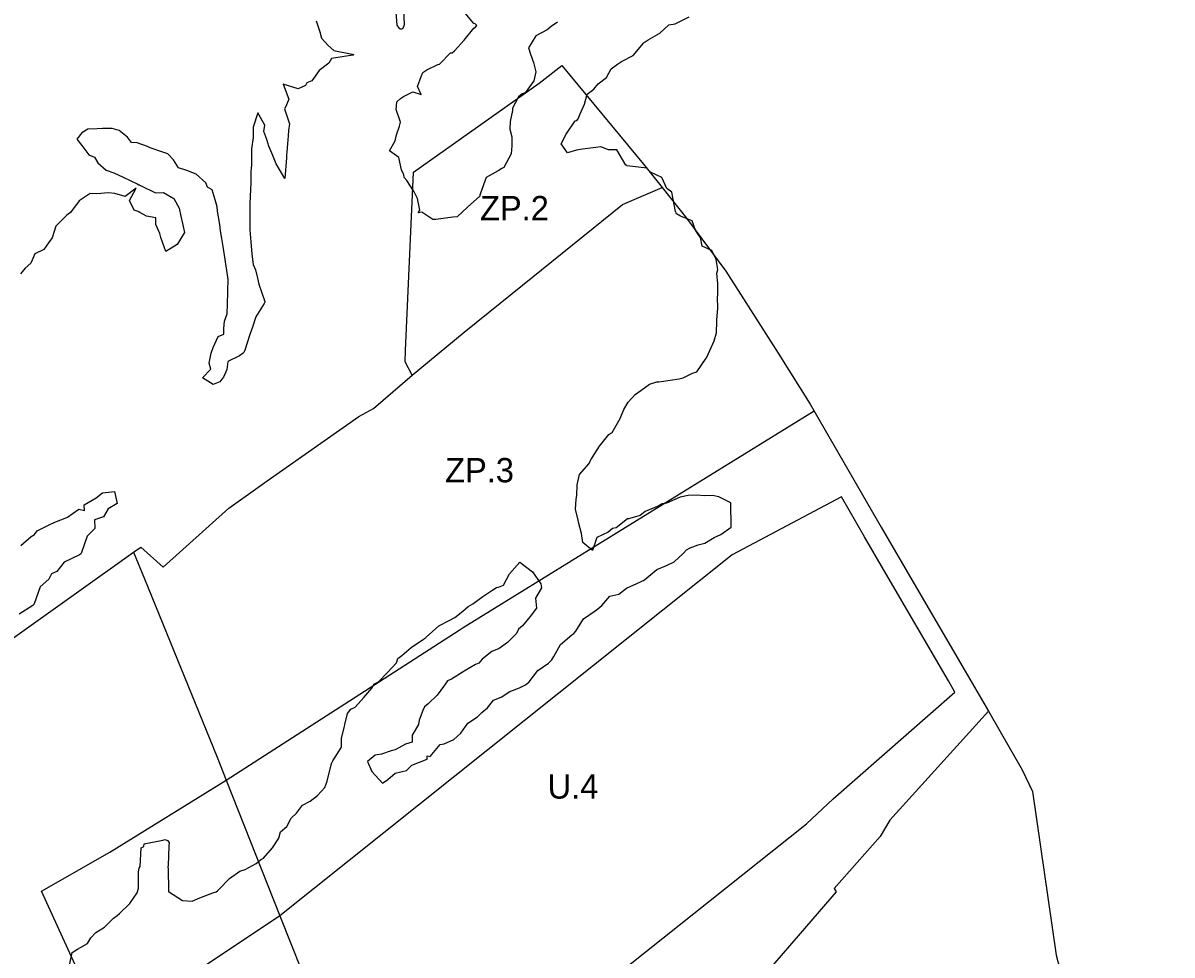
# Model space of a CAD drawing. Extents: x 7423571 to 7425893, y 5544590 to 5545833.
# Drawn here: x 7424591.2 to 7424826.9, y 5545056.2 to 5545247.5 of the extents above; entities that cross this region are included whole.
import ezdxf

# ---------------------------------------------------------------- set-up
doc = ezdxf.new("R2010")
doc.units = 0
for name, color, linetype in [('Default', 7, 'Continuous'), ('linie_rozgraniczające', 7, 'Continuous'), ('linie_zabudowy_nieprzekraczalne', 7, 'Continuous'), ('oznaczenia_przeznaczen', 7, 'Continuous')]:
    doc.layers.add(name, color=color, linetype=linetype)

msp = doc.modelspace()

# ---------------------------------------------------------------- linework, layer by layer
at = {"layer": 'Default'}
for points in [[(7424700.89, 5545247.67), (7424699.56, 5545246.78), (7424698.76, 5545246.07), (7424696.41, 5545244.87), (7424694.93, 5545242.42), (7424695.32, 5545241.07), (7424695.96, 5545239.39), (7424696.42, 5545237.48), (7424696.04, 5545235.6), (7424694.28, 5545233.18), (7424693.65, 5545232.99), (7424692.86, 5545232.33), (7424691.64, 5545230.04), (7424691.68, 5545229.54), (7424691.19, 5545227.26), (7424691.13, 5545225.7), (7424691.52, 5545224.15), (7424691.51, 5545222.27), (7424691.38, 5545220.66), (7424689.89, 5545217.85), (7424689.44, 5545217.64), (7424688.7, 5545217.15), (7424686.24, 5545215.78), (7424685.1, 5545212.58), (7424684.98, 5545212.14), (7424684.98, 5545211.99), (7424682.4, 5545209.71), (7424680.3, 5545207.71), (7424679.41, 5545207.65), (7424675.9, 5545207.21), (7424675.32, 5545207.17), (7424673.08, 5545208.68), (7424672.33, 5545208.56), (7424672.67, 5545209.06), (7424672.19, 5545211.48), (7424671.46, 5545212.83), (7424669.99, 5545215.16), (7424669.42, 5545215.83), (7424669.37, 5545216.36), (7424668.87, 5545217.37), (7424668.35, 5545219.88), (7424666.42, 5545221.25), (7424667.61, 5545223.34), (7424667.84, 5545224.54), (7424668.44, 5545226.33), (7424668.69, 5545227.16), (7424667.8, 5545229.72), (7424667.93, 5545231.32), (7424668.67, 5545231.98), (7424669.29, 5545232.44), (7424671.19, 5545233.39), (7424672.95, 5545232.84), (7424672.19, 5545234.48), (7424672.89, 5545236.52), (7424673.28, 5545237.35), (7424674.07, 5545237.86), (7424676.31, 5545238.95), (7424676.66, 5545239.04), (7424678.93, 5545241.39), (7424679.3, 5545241.41), (7424679.78, 5545241.81), (7424681.75, 5545243.96), (7424683.73, 5545246.47), (7424684.04, 5545246.66), (7424684.32, 5545246.99), (7424684.02, 5545247.3), (7424683.69, 5545247.39), (7424681.62, 5545249.92)], [(7424669.32, 5545250.62), (7424669.4, 5545247.1), (7424669.13, 5545246.38), (7424668.85, 5545246.24), (7424668.73, 5545246.22), (7424668.58, 5545246.21), (7424668.49, 5545246.35), (7424667.96, 5545247.06), (7424667.75, 5545250.53)], [(7424651.36, 5545247.94), (7424652.11, 5545245.69), (7424652.5, 5545244.41), (7424653.85, 5545242.88), (7424654.97, 5545241.88), (7424658.79, 5545241.09), (7424658.93, 5545241.04), (7424658.99, 5545241.02), (7424659.08, 5545240.97), (7424658.96, 5545240.94), (7424658.93, 5545240.93), (7424658.88, 5545240.9), (7424654.54, 5545240.21), (7424654, 5545239.29), (7424652.01, 5545237.72), (7424650.49, 5545235.61), (7424649.49, 5545235.24), (7424649.18, 5545234.67), (7424647.69, 5545233.98), (7424644.59, 5545234.95), (7424645.75, 5545231.87), (7424645.17, 5545230.39), (7424644.88, 5545229.87), (7424645.9, 5545226.83), (7424645.72, 5545225.41), (7424645.62, 5545224.38), (7424645.38, 5545221.04), (7424645.32, 5545220.39), (7424645.3, 5545219.86), (7424644.95, 5545215.57), (7424643.15, 5545218.63), (7424642.49, 5545220.28), (7424641.67, 5545222.24), (7424641.23, 5545223.62), (7424640.65, 5545225.21), (7424640.82, 5545226.54), (7424639.4, 5545229.06), (7424638.49, 5545226.15), (7424638.47, 5545225.12), (7424638.47, 5545223.98), (7424638.09, 5545221.71), (7424638.1, 5545220.1), (7424638.1, 5545218.37), (7424637.99, 5545216.99), (7424638, 5545215.09), (7424637.9, 5545212.94), (7424637.86, 5545212.3), (7424637.77, 5545210.08), (7424637.76, 5545207.58), (7424637.76, 5545207.57), (7424637.76, 5545205.07), (7424637.96, 5545202.59), (7424637.96, 5545202.57), (7424638.18, 5545200.09), (7424638.49, 5545197.92), (7424638.95, 5545196.87), (7424639.33, 5545195.13), (7424639.59, 5545193.91), (7424640.84, 5545190.32), (7424640.87, 5545190.19), (7424640.73, 5545189.92), (7424639.02, 5545187.19), (7424638.33, 5545185.08), (7424637.74, 5545183.56), (7424636.74, 5545180.38), (7424636.61, 5545180.01), (7424636.52, 5545179.88), (7424636.4, 5545179.76), (7424635.65, 5545179.2), (7424633.29, 5545178.05), (7424633.04, 5545176.37), (7424632.34, 5545174.83), (7424632, 5545174.43), (7424631.63, 5545173.9), (7424630.22, 5545173.3), (7424628.07, 5545174.66), (7424629.77, 5545176.48), (7424629.46, 5545177.7), (7424629.87, 5545179.73), (7424630.22, 5545180.88), (7424631.25, 5545183.19), (7424632.42, 5545183.65), (7424632.45, 5545184.84), (7424632.57, 5545186.29), (7424633.11, 5545187.83), (7424633.16, 5545189.88), (7424633.23, 5545192.22), (7424633.24, 5545192.51), (7424633.31, 5545194.89), (7424632.97, 5545197.16), (7424632.91, 5545197.63), (7424632.58, 5545199.86), (7424632.32, 5545201.67), (7424632.03, 5545203.25), (7424631.79, 5545204.83), (7424631.65, 5545206.15), (7424631.16, 5545208.86), (7424631.05, 5545209.81), (7424630.89, 5545210.55), (7424630.03, 5545213.28), (7424629.1, 5545213.82), (7424628.76, 5545214.72), (7424626.74, 5545216.48), (7424624.87, 5545217.24), (7424623.12, 5545217.77), (7424622.12, 5545219.45), (7424620.98, 5545220.65), (7424619.71, 5545221.08), (7424617.33, 5545221.91), (7424616.77, 5545222.13), (7424614.63, 5545222.92), (7424613.53, 5545223.01), (7424612.68, 5545224.07), (7424610.94, 5545225.42), (7424609.51, 5545225.88), (7424607.55, 5545225.83), (7424606.44, 5545225.75), (7424604.51, 5545225.7), (7424603.28, 5545224.95), (7424602.26, 5545223.65), (7424603.29, 5545222.33), (7424604.72, 5545220.47), (7424605.9, 5545219.95), (7424606.61, 5545218.82), (7424608.29, 5545217.32), (7424609.88, 5545216.78), (7424611.77, 5545215.89), (7424614.64, 5545214.47), (7424614.98, 5545214.31), (7424615.14, 5545214.32), (7424615.34, 5545214.17), (7424618.43, 5545212.68), (7424620.05, 5545212.72), (7424622.17, 5545211.52), (7424623.31, 5545209.49), (7424623.62, 5545207.87), (7424624.13, 5545205.73), (7424624.37, 5545204.53), (7424622.88, 5545202.07), (7424620.54, 5545200.63), (7424619.54, 5545203.46), (7424619.34, 5545204.33), (7424618.49, 5545206.12), (7424618.51, 5545207.54), (7424616.61, 5545207.85), (7424615.21, 5545208.64), (7424614.85, 5545208.8), (7424614.07, 5545209.12), (7424613.11, 5545211.08), (7424614.45, 5545213.58), (7424612.19, 5545211.93), (7424610.05, 5545212.53), (7424608.77, 5545212.63), (7424606.41, 5545212.45), (7424605.04, 5545212.52), (7424602.79, 5545210.98), (7424601.01, 5545208.59), (7424600.5, 5545208.28), (7424600.22, 5545208.08), (7424597.95, 5545205.82), (7424597.2, 5545203.43), (7424596.45, 5545202.4), (7424595.5, 5545201.05), (7424593.7, 5545200.12), (7424592.86, 5545198.25), (7424591.67, 5545197.18), (7424590.7, 5545196.02)], [(7424600.81, 5545054.11), (7424601.36, 5545056.79), (7424602.43, 5545057.43), (7424604.45, 5545058.61), (7424605.13, 5545059.75), (7424606.2, 5545060.86), (7424607.94, 5545061.97), (7424609.81, 5545063.83), (7424610.59, 5545064.33), (7424611.04, 5545064.76), (7424613.13, 5545066.8), (7424614.65, 5545069.03), (7424614.92, 5545069.96), (7424614.95, 5545073.3), (7424615.08, 5545074.05), (7424615.29, 5545074.43), (7424615.5, 5545078.25), (7424616.06, 5545078.52), (7424616.12, 5545079.1), (7424619.9, 5545079.79), (7424620.43, 5545079.97), (7424620.89, 5545079.75), (7424621.23, 5545079.31), (7424621.19, 5545078.6), (7424620.99, 5545074.64), (7424620.97, 5545074.29), (7424621, 5545073.97), (7424621.09, 5545069.52), (7424621.11, 5545069.29), (7424623.99, 5545067.46), (7424625.95, 5545067.31), (7424627.5, 5545067.98), (7424630.2, 5545068.98), (7424630.87, 5545069.25), (7424631.17, 5545069.4), (7424631.43, 5545069.71), (7424633.59, 5545071.97), (7424635.71, 5545073.47), (7424636.84, 5545073.79), (7424639.08, 5545075.03), (7424639.93, 5545075.75), (7424640.6, 5545076.15), (7424642.44, 5545078.24), (7424643.74, 5545080.22), (7424644.07, 5545081.55), (7424645.34, 5545082.65), (7424646.24, 5545084.36), (7424647.34, 5545085.37), (7424648.59, 5545087), (7424650.14, 5545087.85), (7424651.63, 5545089.01), (7424653.15, 5545090.61), (7424653.66, 5545091.94), (7424654.45, 5545095.28), (7424654.57, 5545095.67), (7424654.64, 5545095.85), (7424654.8, 5545096.12), (7424656.57, 5545098.88), (7424656.57, 5545100.76), (7424657.17, 5545103.14), (7424657.27, 5545103.55), (7424657.83, 5545105.81), (7424658.52, 5545106.7), (7424659.36, 5545107.13), (7424661.13, 5545109.1), (7424662.83, 5545111.02), (7424663.35, 5545111.87), (7424664.15, 5545112.33), (7424666.01, 5545114.22), (7424667.87, 5545116.23), (7424668.13, 5545117.07), (7424668.94, 5545117.73), (7424670.84, 5545119.38), (7424673.41, 5545121.06), (7424673.8, 5545121.33), (7424673.9, 5545121.37), (7424673.97, 5545121.48), (7424676.51, 5545123.77), (7424678.65, 5545124.92), (7424679.83, 5545125.52), (7424681.49, 5545126.79), (7424682.57, 5545127.8), (7424683.52, 5545128.33), (7424685.59, 5545129.83), (7424687.42, 5545131.04), (7424688.39, 5545131.69), (7424688.77, 5545131.71), (7424689.81, 5545132.13), (7424691.01, 5545134.44), (7424693.18, 5545136.88), (7424695.76, 5545134.87), (7424697.44, 5545132.44), (7424697.59, 5545131.63), (7424696.4, 5545129.48), (7424696.54, 5545127.4), (7424695.28, 5545125.7), (7424693.71, 5545123.81), (7424692.85, 5545123.13), (7424692.47, 5545122.23), (7424690.65, 5545120.36), (7424688.9, 5545119.16), (7424687.41, 5545118.53), (7424685.46, 5545116.94), (7424684.77, 5545116.16), (7424684.03, 5545115.84), (7424681.76, 5545114.47), (7424681.53, 5545114.33), (7424679.14, 5545112.88), (7424678.3, 5545112.51), (7424677.72, 5545111.62), (7424676.23, 5545109.6), (7424674.34, 5545107.82), (7424673.63, 5545107.19), (7424673.24, 5545106.44), (7424672.54, 5545104.47), (7424672.34, 5545103.57), (7424671.04, 5545101.34), (7424671.08, 5545099.92), (7424669.68, 5545099.51), (7424667.58, 5545098.34), (7424666.74, 5545098.18), (7424664.76, 5545097.47), (7424663.51, 5545097.28), (7424661.94, 5545095.97), (7424662.77, 5545093.88), (7424665, 5545091.53), (7424666.08, 5545092.24), (7424667.57, 5545093.55), (7424669.9, 5545094.12), (7424670.99, 5545095.2), (7424674.17, 5545096.47), (7424674.13, 5545097.11), (7424674.78, 5545096.97), (7424676.79, 5545099.47), (7424677.65, 5545099.58), (7424679.65, 5545100.45), (7424680.29, 5545101.06), (7424681.04, 5545101.75), (7424682.47, 5545103.85), (7424684.46, 5545105.11), (7424685.35, 5545106.01), (7424686.52, 5545106.98), (7424687.78, 5545108.57), (7424689.3, 5545109.15), (7424691.12, 5545110.3), (7424693.07, 5545111.09), (7424694.2, 5545111.64), (7424694.62, 5545111.89), (7424695.07, 5545112.33), (7424696.85, 5545114.64), (7424699.03, 5545116.15), (7424699.71, 5545116.8), (7424700.15, 5545117.54), (7424701.53, 5545119.94), (7424703.79, 5545121.95), (7424704.23, 5545122.26), (7424704.67, 5545122.72), (7424706.18, 5545125.27), (7424708.6, 5545126.87), (7424709.17, 5545127.32), (7424709.97, 5545127.94), (7424711.59, 5545129.9), (7424713.46, 5545130.32), (7424715.06, 5545131.51), (7424717.91, 5545132.82), (7424718.35, 5545133.06), (7424718.53, 5545133.12), (7424718.78, 5545133.3), (7424721.29, 5545135.38), (7424723.23, 5545136.18), (7424724.79, 5545136.96), (7424726.68, 5545138.63), (7424727.35, 5545139.41), (7424728.09, 5545139.78), (7424729.75, 5545140.44), (7424731.09, 5545140.77), (7424733, 5545141.95), (7424734.41, 5545142.51), (7424736.47, 5545144.03), (7424736.49, 5545145.41), (7424736.41, 5545147.66), (7424736.42, 5545149.03), (7424733.97, 5545150.24), (7424732.66, 5545150.53), (7424730.99, 5545150.48), (7424729.51, 5545150.61), (7424727.65, 5545150.56), (7424726.07, 5545150.21), (7424723.21, 5545148.99), (7424722.72, 5545148.85), (7424722.38, 5545148.8), (7424721.67, 5545148.43), (7424718.84, 5545147.26), (7424717.81, 5545146.46), (7424715.42, 5545145.76), (7424715.23, 5545145.77), (7424712.91, 5545143.88), (7424712.16, 5545143.8), (7424711.27, 5545143.01), (7424708.95, 5545141.95), (7424708.09, 5545139.29), (7424706.11, 5545140.88), (7424705.77, 5545142.78), (7424705.19, 5545145.09), (7424705.1, 5545145.5), (7424704.55, 5545147.74), (7424704.68, 5545149.76), (7424704.88, 5545150.51), (7424704.93, 5545152.76), (7424705.41, 5545154.83), (7424707.37, 5545157.13), (7424707.61, 5545157.61), (7424707.7, 5545157.87), (7424708.52, 5545159.14), (7424709.47, 5545160.7), (7424711.43, 5545163.03), (7424711.81, 5545163.36), (7424712.12, 5545163.48), (7424713.76, 5545166.37), (7424714.47, 5545168.16), (7424715.35, 5545169.71), (7424716.8, 5545171.27), (7424718, 5545172.08), (7424719.72, 5545173.37), (7424721.24, 5545173.89), (7424721.7, 5545173.85), (7424722.16, 5545173.94), (7424725.82, 5545174.48), (7424726.67, 5545174.66), (7424728.57, 5545175.67), (7424729.47, 5545175.93), (7424731.36, 5545178.7), (7424731.48, 5545178.85), (7424731.49, 5545178.87), (7424731.5, 5545178.93), (7424733.03, 5545182.26), (7424733.49, 5545183.94), (7424733.59, 5545186.33), (7424733.57, 5545186.57), (7424733.74, 5545188.95), (7424733.73, 5545191.23), (7424733.78, 5545191.75), (7424733.79, 5545193.96), (7424733.57, 5545196.19), (7424733.74, 5545196.92), (7424733.42, 5545198.95), (7424732.52, 5545200.82), (7424730.58, 5545201.68), (7424730.18, 5545203.49), (7424729.97, 5545203.81), (7424729.21, 5545205.02), (7424728.5, 5545206.89), (7424726.1, 5545207.88), (7424725.31, 5545208.37), (7424725.22, 5545208.54), (7424725.17, 5545208.62), (7424725.07, 5545208.83), (7424724.34, 5545212.81), (7424723.32, 5545213.55), (7424722.27, 5545215.78), (7424719.96, 5545216.86), (7424719.21, 5545217.68), (7424715.14, 5545218.22), (7424715, 5545218.33), (7424714.89, 5545218.36), (7424713.07, 5545221.45), (7424711.36, 5545221.47), (7424709.74, 5545222.08), (7424708.71, 5545221.93), (7424706.02, 5545221.59), (7424704.76, 5545221.41), (7424702.92, 5545220.87), (7424701.64, 5545222.68), (7424702.67, 5545224.68), (7424704.52, 5545227.42), (7424704.84, 5545227.49), (7424705.1, 5545227.82), (7424705.51, 5545228.89), (7424706.43, 5545230.83), (7424706.96, 5545232.9), (7424708.31, 5545233.91), (7424709.21, 5545235.05), (7424710.91, 5545236.32), (7424711.87, 5545238.1), (7424713.19, 5545239.02), (7424714.03, 5545239.58), (7424716.42, 5545240.85), (7424718.5, 5545243.38), (7424718.7, 5545243.55), (7424718.87, 5545243.64), (7424719.47, 5545244.03), (7424721.9, 5545245.42), (7424723.73, 5545247.1), (7424725.02, 5545247.35), (7424727.86, 5545248.76)], [(7424590.82, 5545140.27), (7424592.89, 5545142.1), (7424593.6, 5545142.51), (7424594.13, 5545143.26), (7424596.6, 5545144.55), (7424597.77, 5545145.08), (7424600.22, 5545146.02), (7424600.34, 5545146.12), (7424602.67, 5545147.76), (7424603.89, 5545147.45), (7424603.81, 5545148.65), (7424606.24, 5545150.09), (7424607.54, 5545151.08), (7424610, 5545151.38), (7424610.56, 5545148.93), (7424608.7, 5545147.83), (7424607.74, 5545146.16), (7424605.94, 5545145.56), (7424605.99, 5545143.74), (7424604.39, 5545142.17), (7424603.27, 5545138.86), (7424603.15, 5545138.62), (7424603.1, 5545138.56), (7424603.04, 5545138.51), (7424602.81, 5545138.36), (7424599.72, 5545136.87), (7424598.18, 5545134.98), (7424597.08, 5545134.5), (7424596.54, 5545133.35), (7424594.78, 5545131.8), (7424593.56, 5545128.34), (7424593.5, 5545128.22), (7424593.49, 5545128.19), (7424593.46, 5545128.16), (7424593.24, 5545127.99), (7424590.45, 5545126.18)]]:
    msp.add_lwpolyline(points, dxfattribs=at)
at = {"layer": 'linie_rozgraniczające'}
for points in [[(7424671.1, 5545175.25), (7424669.63, 5545178), (7424669.73, 5545180.29), (7424671.33, 5545216.88), (7424697.12, 5545235.14), (7424701.78, 5545238.79), (7424718.51, 5545218.53), (7424722.34, 5545213.75)], [(7424671.1, 5545175.25), (7424681.76, 5545184.09), (7424691.56, 5545192), (7424714.24, 5545210.29), (7424722.34, 5545213.75)], [(7424722.34, 5545213.75), (7424727.36, 5545207.48), (7424735.41, 5545196.6), (7424746.11, 5545179.72), (7424752.73, 5545169.28), (7424767.3, 5545144.05), (7424771.19, 5545137.36), (7424784.52, 5545114.5), (7424789.29, 5545106.29)], [(7424613.92, 5545138.89), (7424615.39, 5545139.93), (7424620.01, 5545135.85), (7424633.49, 5545147.94), (7424639.43, 5545152.2), (7424641.35, 5545153.56), (7424660.1, 5545166.77), (7424663.14, 5545168.39), (7424671.1, 5545175.25)], [(7424632.92, 5545092.15), (7424657.24, 5545107.82), (7424680.7, 5545122.89), (7424681.54, 5545123.43), (7424753.53, 5545167.9)], [(7424510.23, 5545014.49), (7424505.42, 5545026.19), (7424509.67, 5545031.79), (7424519.51, 5545041.02), (7424545.99, 5545074.08), (7424548.87, 5545077.67), (7424573.07, 5545087.42), (7424579.84, 5545090.14), (7424570.85, 5545108.27), (7424590.52, 5545122.25), (7424613.92, 5545138.89)], [(7424613.92, 5545138.89), (7424616.14, 5545133.44), (7424631.07, 5545096.82), (7424632.92, 5545092.15)], [(7424789.29, 5545106.29), (7424775.58, 5545091.16)], [(7424789.29, 5545106.29), (7424796.18, 5545094.27), (7424798.34, 5545089.81), (7424803.18, 5545056.25)], [(7424624.93, 5545001.63), (7424615.09, 5545025.48), (7424595.04, 5545069.35), (7424609.07, 5545077.36), (7424632.92, 5545092.15)], [(7424632.92, 5545092.15), (7424643.95, 5545064.26), (7424650.55, 5545047.57), (7424663.93, 5545013.46)], [(7424775.58, 5545091.16), (7424769.05, 5545083.95), (7424767.05, 5545080.56), (7424757.66, 5545069.92), (7424758.07, 5545069.2), (7424732, 5545039.05), (7424727.68, 5545037), (7424714.63, 5545023.76)], [(7424803.18, 5545056.25), (7424803.93, 5545053.38), (7424814.96, 5545026.45), (7424826.93, 5545010.87), (7424819.62, 5545002.17), (7424791.84, 5544975.38), (7424741.71, 5544916.05), (7424741.07, 5544915.24), (7424740.42, 5544914.42), (7424732.44, 5544904.28), (7424724.47, 5544894.13), (7424733.19, 5544872.33), (7424717.72, 5544854.88)]]:
    msp.add_lwpolyline(points, dxfattribs=at)
at = {"layer": 'linie_zabudowy_nieprzekraczalne'}
msp.add_lwpolyline([(7424678.59, 5545024.29), (7424691.07, 5545034.32), (7424702.72, 5545043.98), (7424751.98, 5545083.18), (7424757.42, 5545088.33), (7424782.39, 5545110.2), (7424781.06, 5545112.49), (7424781.06, 5545112.49), (7424767.73, 5545135.35), (7424763.84, 5545142.04), (7424763.84, 5545142.05), (7424759.11, 5545150.24), (7424736.71, 5545138.34), (7424643.95, 5545064.26), (7424611.62, 5545042.69), (7424618.76, 5545027.07), (7424626.56, 5545008.17), (7424678.57, 5545024.27)], dxfattribs=at)

# ---------------------------------------------------------------- texts
at = {"layer": 'oznaczenia_przeznaczen'}
for s, p in [('ZP.2', (7424684.99, 5545207.01)), ('ZP.3', (7424677.83, 5545153.24)), ('U.4', (7424698.85, 5545088.34))]:
    msp.add_text(s, height=5, dxfattribs=at).set_placement(p)

doc.saveas('drawing.dxf')
